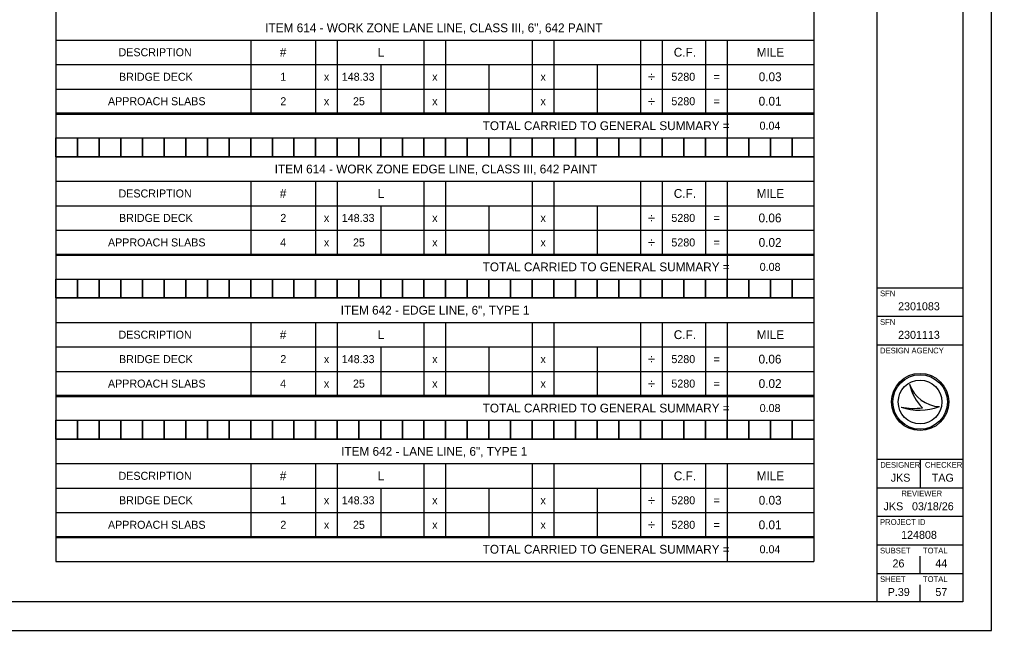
# Model space of a CAD drawing. Extents: x 0 to 34, y 0 to 22.
# Drawn here: x 17 to 34, y 0 to 10.69 of the extents above; entities that cross this region are included whole.
import ezdxf

# ---------------------------------------------------------------- set-up
doc = ezdxf.new("R2010")
doc.units = 0
for name, color, linetype in [('SH_Border', 7, 'Continuous'), ('SH_Cut_Line', 7, 'Continuous'), ('SH_Data', 7, 'Continuous'), ('SH_Text', 7, 'Continuous')]:
    doc.layers.add(name, color=color, linetype=linetype)

msp = doc.modelspace()

# ---------------------------------------------------------------- linework, layer by layer
at = {"layer": 'SH_Border'}
for p, q in [((32, 0.5), (32, 21.5)), ((32, 6), (33.5, 6)), ((32, 5.5), (33.5, 5.5)), ((32, 5), (33.5, 5)), ((32, 3), (33.5, 3)), ((32.75, 3), (32.75, 2.5)), ((32, 2.5), (33.5, 2.5)), ((32, 2), (33.5, 2)), ((32, 1.5), (33.5, 1.5)), ((32, 1), (33.5, 1))]:
    msp.add_line(p, q, dxfattribs=at)
msp.add_lwpolyline([(1.5, 21.5), (33.5, 21.5), (33.5, 0.5), (1.5, 0.5)], close=True, dxfattribs=at)
at = {"layer": 'SH_Cut_Line'}
msp.add_lwpolyline([(0, 0), (34, 0), (34, 22), (0, 22)], close=True, dxfattribs=at)
at = {"layer": 'SH_Data'}
for p, q in [((32.75, 5.675), (32.75, 5.675)), ((32.75, 5.175), (32.75, 5.175)), ((32.567, 4.31), (32.567, 4.31)), ((32.75, 4), (32.75, 4)), ((33.087, 3.919), (33.087, 3.919)), ((32.417, 3.91), (32.417, 3.91)), ((32.75, 1), (32.75, 1.3)), ((32.75, 0.5), (32.75, 0.8)), ((32.375, 0.675), (32.375, 0.675))]:
    msp.add_line(p, q, dxfattribs=at)
for radius in [0.5, 0.477, 0.477, 0.382]:
    msp.add_circle((32.75, 4), radius, dxfattribs=at)
for centre, radius, start, end in [((33.116, 4.498), 0.58, 198.9257, 198.9319), ((33.347, 4.47), 0.796, 191.6379, 191.6421), ((33.116, 4.498), 0.58, 198.9319, 267.1657), ((33.347, 4.47), 0.796, 191.6421, 226.0947), ((32.739, 4.87), 1.013, 251.4576, 290.0832), ((32.648, 5.154), 1.266, 259.4964, 259.4995), ((32.739, 4.87), 1.013, 251.4527, 251.4576), ((32.648, 5.154), 1.266, 259.4995, 276.6672)]:
    msp.add_arc(centre, radius, start, end, dxfattribs=at)
at = {"layer": 'SH_Text'}
for p, q in [((17.634, 11.531), (17.634, 9.038)), ((30.893, 11.531), (30.893, 9.038)), ((17.634, 10.334), (30.893, 10.334)), ((21.044, 10.334), (21.044, 9.06)), ((22.18, 10.334), (22.18, 9.06)), ((22.559, 10.334), (22.559, 9.06)), ((24.074, 10.334), (24.074, 9.06)), ((24.453, 10.334), (24.453, 9.06)), ((25.968, 10.334), (25.968, 9.06)), ((26.347, 10.334), (26.347, 9.06)), ((27.863, 10.334), (27.863, 9.06)), ((28.241, 10.334), (28.241, 9.06)), ((28.999, 10.334), (28.999, 9.06)), ((29.378, 10.334), (29.378, 9.06)), ((17.634, 9.905), (30.893, 9.905)), ((23.317, 9.905), (23.317, 9.06)), ((25.211, 9.905), (25.211, 9.06)), ((27.105, 9.905), (27.105, 9.06)), ((17.634, 9.477), (30.893, 9.477)), ((17.634, 9.06), (30.893, 9.06)), ((17.634, 9.06), (17.634, 6.567)), ((17.634, 9.038), (30.893, 9.038)), ((29.378, 9.038), (29.378, 8.621)), ((30.893, 9.06), (30.893, 6.567)), ((17.634, 8.621), (30.893, 8.621)), ((17.634, 8.291), (30.893, 8.291)), ((17.634, 7.863), (30.893, 7.863)), ((21.044, 7.863), (21.044, 6.589)), ((22.18, 7.863), (22.18, 6.589)), ((22.559, 7.863), (22.559, 6.589)), ((24.074, 7.863), (24.074, 6.589)), ((24.453, 7.863), (24.453, 6.589)), ((25.968, 7.863), (25.968, 6.589)), ((26.347, 7.863), (26.347, 6.589)), ((27.863, 7.863), (27.863, 6.589)), ((28.241, 7.863), (28.241, 6.589)), ((28.999, 7.863), (28.999, 6.589)), ((29.378, 7.863), (29.378, 6.589)), ((17.634, 7.435), (30.893, 7.435)), ((23.317, 7.435), (23.317, 6.589)), ((25.211, 7.435), (25.211, 6.589)), ((27.105, 7.435), (27.105, 6.589)), ((17.634, 7.007), (30.893, 7.007)), ((17.634, 6.589), (30.893, 6.589)), ((17.634, 6.589), (17.634, 4.097)), ((17.634, 6.567), (30.893, 6.567)), ((29.378, 6.567), (29.378, 6.15)), ((30.893, 6.589), (30.893, 4.097)), ((17.634, 6.15), (30.893, 6.15)), ((17.634, 5.821), (30.893, 5.821)), ((17.634, 5.392), (30.893, 5.392)), ((21.044, 5.392), (21.044, 4.119)), ((22.18, 5.392), (22.18, 4.119)), ((22.559, 5.392), (22.559, 4.119)), ((24.074, 5.392), (24.074, 4.119)), ((24.453, 5.392), (24.453, 4.119)), ((25.968, 5.392), (25.968, 4.119)), ((26.347, 5.392), (26.347, 4.119)), ((27.863, 5.392), (27.863, 4.119)), ((28.241, 5.392), (28.241, 4.119)), ((28.999, 5.392), (28.999, 4.119)), ((29.378, 5.392), (29.378, 4.119)), ((17.634, 4.964), (30.893, 4.964)), ((23.317, 4.964), (23.317, 4.119)), ((25.211, 4.964), (25.211, 4.119)), ((27.105, 4.964), (27.105, 4.119)), ((17.634, 4.536), (30.893, 4.536)), ((17.634, 4.119), (30.893, 4.119)), ((17.634, 4.119), (17.634, 1.626)), ((17.634, 4.097), (30.893, 4.097)), ((29.378, 4.097), (29.378, 3.68)), ((30.893, 4.119), (30.893, 1.626)), ((17.634, 3.68), (30.893, 3.68)), ((17.634, 3.35), (30.893, 3.35)), ((17.634, 2.922), (30.893, 2.922)), ((21.044, 2.922), (21.044, 1.648)), ((22.18, 2.922), (22.18, 1.648)), ((22.559, 2.922), (22.559, 1.648)), ((24.074, 2.922), (24.074, 1.648)), ((24.453, 2.922), (24.453, 1.648)), ((25.968, 2.922), (25.968, 1.648)), ((26.347, 2.922), (26.347, 1.648)), ((27.863, 2.922), (27.863, 1.648)), ((28.241, 2.922), (28.241, 1.648)), ((28.999, 2.922), (28.999, 1.648)), ((29.378, 2.922), (29.378, 1.648)), ((17.634, 2.494), (30.893, 2.494)), ((23.317, 2.494), (23.317, 1.648)), ((25.211, 2.494), (25.211, 1.648)), ((27.105, 2.494), (27.105, 1.648)), ((17.634, 2.065), (30.893, 2.065)), ((17.634, 1.648), (30.893, 1.648)), ((17.634, 1.648), (17.634, 1.209)), ((17.634, 1.626), (30.893, 1.626)), ((29.378, 1.626), (29.378, 1.209)), ((30.893, 1.648), (30.893, 1.209)), ((17.634, 1.209), (30.893, 1.209))]:
    msp.add_line(p, q, dxfattribs=at)
for points in [[(17.634, 8.621), (18.013, 8.621), (18.013, 8.291), (17.634, 8.291)], [(18.013, 8.621), (18.392, 8.621), (18.392, 8.291), (18.013, 8.291)], [(18.392, 8.621), (18.771, 8.621), (18.771, 8.291), (18.392, 8.291)], [(18.771, 8.621), (19.15, 8.621), (19.15, 8.291), (18.771, 8.291)], [(19.15, 8.621), (19.528, 8.621), (19.528, 8.291), (19.15, 8.291)], [(19.528, 8.621), (19.907, 8.621), (19.907, 8.291), (19.528, 8.291)], [(19.907, 8.621), (20.286, 8.621), (20.286, 8.291), (19.907, 8.291)], [(20.286, 8.621), (20.665, 8.621), (20.665, 8.291), (20.286, 8.291)], [(20.665, 8.621), (21.044, 8.621), (21.044, 8.291), (20.665, 8.291)], [(21.044, 8.621), (21.423, 8.621), (21.423, 8.291), (21.044, 8.291)], [(21.423, 8.621), (21.801, 8.621), (21.801, 8.291), (21.423, 8.291)], [(21.801, 8.621), (22.18, 8.621), (22.18, 8.291), (21.801, 8.291)], [(22.18, 8.621), (22.559, 8.621), (22.559, 8.291), (22.18, 8.291)], [(22.559, 8.621), (22.938, 8.621), (22.938, 8.291), (22.559, 8.291)], [(22.938, 8.621), (23.317, 8.621), (23.317, 8.291), (22.938, 8.291)], [(23.317, 8.621), (23.696, 8.621), (23.696, 8.291), (23.317, 8.291)], [(23.696, 8.621), (24.074, 8.621), (24.074, 8.291), (23.696, 8.291)], [(24.074, 8.621), (24.453, 8.621), (24.453, 8.291), (24.074, 8.291)], [(24.453, 8.621), (24.832, 8.621), (24.832, 8.291), (24.453, 8.291)], [(24.832, 8.621), (25.211, 8.621), (25.211, 8.291), (24.832, 8.291)], [(25.211, 8.621), (25.59, 8.621), (25.59, 8.291), (25.211, 8.291)], [(25.59, 8.621), (25.968, 8.621), (25.968, 8.291), (25.59, 8.291)], [(25.968, 8.621), (26.347, 8.621), (26.347, 8.291), (25.968, 8.291)], [(26.347, 8.621), (26.726, 8.621), (26.726, 8.291), (26.347, 8.291)], [(26.726, 8.621), (27.105, 8.621), (27.105, 8.291), (26.726, 8.291)], [(27.105, 8.621), (27.484, 8.621), (27.484, 8.291), (27.105, 8.291)], [(27.484, 8.621), (27.863, 8.621), (27.863, 8.291), (27.484, 8.291)], [(27.863, 8.621), (28.241, 8.621), (28.241, 8.291), (27.863, 8.291)], [(28.241, 8.621), (28.62, 8.621), (28.62, 8.291), (28.241, 8.291)], [(28.62, 8.621), (28.999, 8.621), (28.999, 8.291), (28.62, 8.291)], [(28.999, 8.621), (29.378, 8.621), (29.378, 8.291), (28.999, 8.291)], [(29.378, 8.621), (29.757, 8.621), (29.757, 8.291), (29.378, 8.291)], [(29.757, 8.621), (30.136, 8.621), (30.136, 8.291), (29.757, 8.291)], [(30.136, 8.621), (30.514, 8.621), (30.514, 8.291), (30.136, 8.291)], [(30.514, 8.621), (30.893, 8.621), (30.893, 8.291), (30.514, 8.291)], [(17.634, 6.15), (18.013, 6.15), (18.013, 5.821), (17.634, 5.821)], [(18.013, 6.15), (18.392, 6.15), (18.392, 5.821), (18.013, 5.821)], [(18.392, 6.15), (18.771, 6.15), (18.771, 5.821), (18.392, 5.821)], [(18.771, 6.15), (19.15, 6.15), (19.15, 5.821), (18.771, 5.821)], [(19.15, 6.15), (19.528, 6.15), (19.528, 5.821), (19.15, 5.821)], [(19.528, 6.15), (19.907, 6.15), (19.907, 5.821), (19.528, 5.821)], [(19.907, 6.15), (20.286, 6.15), (20.286, 5.821), (19.907, 5.821)], [(20.286, 6.15), (20.665, 6.15), (20.665, 5.821), (20.286, 5.821)], [(20.665, 6.15), (21.044, 6.15), (21.044, 5.821), (20.665, 5.821)], [(21.044, 6.15), (21.423, 6.15), (21.423, 5.821), (21.044, 5.821)], [(21.423, 6.15), (21.801, 6.15), (21.801, 5.821), (21.423, 5.821)], [(21.801, 6.15), (22.18, 6.15), (22.18, 5.821), (21.801, 5.821)], [(22.18, 6.15), (22.559, 6.15), (22.559, 5.821), (22.18, 5.821)], [(22.559, 6.15), (22.938, 6.15), (22.938, 5.821), (22.559, 5.821)], [(22.938, 6.15), (23.317, 6.15), (23.317, 5.821), (22.938, 5.821)], [(23.317, 6.15), (23.696, 6.15), (23.696, 5.821), (23.317, 5.821)], [(23.696, 6.15), (24.074, 6.15), (24.074, 5.821), (23.696, 5.821)], [(24.074, 6.15), (24.453, 6.15), (24.453, 5.821), (24.074, 5.821)], [(24.453, 6.15), (24.832, 6.15), (24.832, 5.821), (24.453, 5.821)], [(24.832, 6.15), (25.211, 6.15), (25.211, 5.821), (24.832, 5.821)], [(25.211, 6.15), (25.59, 6.15), (25.59, 5.821), (25.211, 5.821)], [(25.59, 6.15), (25.968, 6.15), (25.968, 5.821), (25.59, 5.821)], [(25.968, 6.15), (26.347, 6.15), (26.347, 5.821), (25.968, 5.821)], [(26.347, 6.15), (26.726, 6.15), (26.726, 5.821), (26.347, 5.821)], [(26.726, 6.15), (27.105, 6.15), (27.105, 5.821), (26.726, 5.821)], [(27.105, 6.15), (27.484, 6.15), (27.484, 5.821), (27.105, 5.821)], [(27.484, 6.15), (27.863, 6.15), (27.863, 5.821), (27.484, 5.821)], [(27.863, 6.15), (28.241, 6.15), (28.241, 5.821), (27.863, 5.821)], [(28.241, 6.15), (28.62, 6.15), (28.62, 5.821), (28.241, 5.821)], [(28.62, 6.15), (28.999, 6.15), (28.999, 5.821), (28.62, 5.821)], [(28.999, 6.15), (29.378, 6.15), (29.378, 5.821), (28.999, 5.821)], [(29.378, 6.15), (29.757, 6.15), (29.757, 5.821), (29.378, 5.821)], [(29.757, 6.15), (30.136, 6.15), (30.136, 5.821), (29.757, 5.821)], [(30.136, 6.15), (30.514, 6.15), (30.514, 5.821), (30.136, 5.821)], [(30.514, 6.15), (30.893, 6.15), (30.893, 5.821), (30.514, 5.821)], [(17.634, 3.68), (18.013, 3.68), (18.013, 3.35), (17.634, 3.35)], [(18.013, 3.68), (18.392, 3.68), (18.392, 3.35), (18.013, 3.35)], [(18.392, 3.68), (18.771, 3.68), (18.771, 3.35), (18.392, 3.35)], [(18.771, 3.68), (19.15, 3.68), (19.15, 3.35), (18.771, 3.35)], [(19.15, 3.68), (19.528, 3.68), (19.528, 3.35), (19.15, 3.35)], [(19.528, 3.68), (19.907, 3.68), (19.907, 3.35), (19.528, 3.35)], [(19.907, 3.68), (20.286, 3.68), (20.286, 3.35), (19.907, 3.35)], [(20.286, 3.68), (20.665, 3.68), (20.665, 3.35), (20.286, 3.35)], [(20.665, 3.68), (21.044, 3.68), (21.044, 3.35), (20.665, 3.35)], [(21.044, 3.68), (21.423, 3.68), (21.423, 3.35), (21.044, 3.35)], [(21.423, 3.68), (21.801, 3.68), (21.801, 3.35), (21.423, 3.35)], [(21.801, 3.68), (22.18, 3.68), (22.18, 3.35), (21.801, 3.35)], [(22.18, 3.68), (22.559, 3.68), (22.559, 3.35), (22.18, 3.35)], [(22.559, 3.68), (22.938, 3.68), (22.938, 3.35), (22.559, 3.35)], [(22.938, 3.68), (23.317, 3.68), (23.317, 3.35), (22.938, 3.35)], [(23.317, 3.68), (23.696, 3.68), (23.696, 3.35), (23.317, 3.35)], [(23.696, 3.68), (24.074, 3.68), (24.074, 3.35), (23.696, 3.35)], [(24.074, 3.68), (24.453, 3.68), (24.453, 3.35), (24.074, 3.35)], [(24.453, 3.68), (24.832, 3.68), (24.832, 3.35), (24.453, 3.35)], [(24.832, 3.68), (25.211, 3.68), (25.211, 3.35), (24.832, 3.35)], [(25.211, 3.68), (25.59, 3.68), (25.59, 3.35), (25.211, 3.35)], [(25.59, 3.68), (25.968, 3.68), (25.968, 3.35), (25.59, 3.35)], [(25.968, 3.68), (26.347, 3.68), (26.347, 3.35), (25.968, 3.35)], [(26.347, 3.68), (26.726, 3.68), (26.726, 3.35), (26.347, 3.35)], [(26.726, 3.68), (27.105, 3.68), (27.105, 3.35), (26.726, 3.35)], [(27.105, 3.68), (27.484, 3.68), (27.484, 3.35), (27.105, 3.35)], [(27.484, 3.68), (27.863, 3.68), (27.863, 3.35), (27.484, 3.35)], [(27.863, 3.68), (28.241, 3.68), (28.241, 3.35), (27.863, 3.35)], [(28.241, 3.68), (28.62, 3.68), (28.62, 3.35), (28.241, 3.35)], [(28.62, 3.68), (28.999, 3.68), (28.999, 3.35), (28.62, 3.35)], [(28.999, 3.68), (29.378, 3.68), (29.378, 3.35), (28.999, 3.35)], [(29.378, 3.68), (29.757, 3.68), (29.757, 3.35), (29.378, 3.35)], [(29.757, 3.68), (30.136, 3.68), (30.136, 3.35), (29.757, 3.35)], [(30.136, 3.68), (30.514, 3.68), (30.514, 3.35), (30.136, 3.35)], [(30.514, 3.68), (30.893, 3.68), (30.893, 3.35), (30.514, 3.35)]]:
    msp.add_lwpolyline(points, close=True, dxfattribs=at)

# ---------------------------------------------------------------- texts
at = {"layer": 'SH_Data'}
for s, height, p in [('SFN', 0.1, (32.05, 5.85)), ('2301083', 0.14, (32.366, 5.605)), ('SFN', 0.1, (32.05, 5.35)), ('2301113', 0.14, (32.366, 5.105)), ('DESIGN AGENCY', 0.1, (32.05, 4.85)), ('DESIGNER', 0.1, (32.054, 2.85)), ('CHECKER', 0.1, (32.835, 2.85)), ('JKS', 0.14, (32.237, 2.605)), ('TAG', 0.14, (32.955, 2.605)), ('REVIEWER', 0.1, (32.422, 2.35)), ('JKS', 0.14, (32.112, 2.105)), ('03/18/26', 0.14, (32.609, 2.105)), ('PROJECT ID', 0.1, (32.05, 1.85)), ('124808', 0.14, (32.419, 1.605)), ('SUBSET', 0.1, (32.05, 1.35)), ('TOTAL', 0.1, (32.8, 1.35)), ('26', 0.14, (32.268, 1.105)), ('44', 0.14, (33.016, 1.105)), ('SHEET', 0.1, (32.05, 0.85)), ('TOTAL', 0.1, (32.8, 0.85)), ('P.39', 0.14, (32.184, 0.605)), ('57', 0.14, (33.018, 0.605))]:
    msp.add_text(s, height=height, dxfattribs=at).set_placement(p)
at = {"layer": 'SH_Text'}
for s, height, p in [('ITEM 614 - WORK ZONE LANE LINE, CLASS III, 6", 642 PAINT', 0.154, (21.299, 10.471)), ('DESCRIPTION', 0.14, (18.733, 10.05)), ('#', 0.154, (21.553, 10.043)), ('L', 0.154, (23.266, 10.043)), ('C.F.', 0.154, (28.443, 10.043)), ('MILE', 0.154, (29.892, 10.043)), ('BRIDGE DECK', 0.14, (18.741, 9.621)), ('1', 0.14, (21.562, 9.621)), ('x', 0.14, (22.324, 9.621)), ('148.33', 0.14, (22.637, 9.621)), ('x', 0.14, (24.218, 9.621)), ('x', 0.14, (26.112, 9.621)), ('÷', 0.168, (27.99, 9.607)), ('5280', 0.14, (28.401, 9.621)), ('=', 0.14, (29.139, 9.621)), ('0.03', 0.154, (29.928, 9.614)), ('APPROACH SLABS', 0.14, (18.548, 9.193)), ('2', 0.14, (21.562, 9.193)), ('x', 0.14, (22.324, 9.193)), ('25', 0.14, (22.833, 9.193)), ('x', 0.14, (24.218, 9.193)), ('x', 0.14, (26.112, 9.193)), ('÷', 0.168, (27.99, 9.179)), ('5280', 0.14, (28.401, 9.193)), ('=', 0.14, (29.139, 9.193)), ('0.01', 0.154, (29.927, 9.186)), ('TOTAL CARRIED TO GENERAL SUMMARY =', 0.154, (25.101, 8.758)), ('0.04', 0.14, (29.943, 8.765)), ('ITEM 614 - WORK ZONE EDGE LINE, CLASS III, 642 PAINT', 0.154, (21.464, 8)), ('DESCRIPTION', 0.14, (18.733, 7.579)), ('#', 0.154, (21.553, 7.572)), ('L', 0.154, (23.266, 7.572)), ('C.F.', 0.154, (28.443, 7.572)), ('MILE', 0.154, (29.892, 7.572)), ('BRIDGE DECK', 0.14, (18.741, 7.151)), ('2', 0.14, (21.562, 7.151)), ('x', 0.14, (22.324, 7.151)), ('148.33', 0.14, (22.637, 7.151)), ('x', 0.14, (24.218, 7.151)), ('x', 0.14, (26.112, 7.151)), ('÷', 0.168, (27.99, 7.137)), ('5280', 0.14, (28.401, 7.151)), ('=', 0.14, (29.139, 7.151)), ('0.06', 0.154, (29.925, 7.144)), ('APPROACH SLABS', 0.14, (18.548, 6.722)), ('4', 0.14, (21.559, 6.722)), ('x', 0.14, (22.324, 6.722)), ('25', 0.14, (22.833, 6.722)), ('x', 0.14, (24.218, 6.722)), ('x', 0.14, (26.112, 6.722)), ('÷', 0.168, (27.99, 6.708)), ('5280', 0.14, (28.401, 6.722)), ('=', 0.14, (29.139, 6.722)), ('0.02', 0.154, (29.927, 6.715)), ('TOTAL CARRIED TO GENERAL SUMMARY =', 0.154, (25.101, 6.287)), ('0.08', 0.14, (29.945, 6.294)), ('ITEM 642 - EDGE LINE, 6", TYPE 1', 0.154, (22.618, 5.53)), ('DESCRIPTION', 0.14, (18.733, 5.108)), ('#', 0.154, (21.553, 5.101)), ('L', 0.154, (23.266, 5.101)), ('C.F.', 0.154, (28.443, 5.101)), ('MILE', 0.154, (29.892, 5.101)), ('BRIDGE DECK', 0.14, (18.741, 4.68)), ('2', 0.14, (21.562, 4.68)), ('x', 0.14, (22.324, 4.68)), ('148.33', 0.14, (22.637, 4.68)), ('x', 0.14, (24.218, 4.68)), ('x', 0.14, (26.112, 4.68)), ('÷', 0.168, (27.99, 4.666)), ('5280', 0.14, (28.401, 4.68)), ('=', 0.14, (29.139, 4.68)), ('0.06', 0.154, (29.925, 4.673)), ('APPROACH SLABS', 0.14, (18.548, 4.252)), ('4', 0.14, (21.559, 4.252)), ('x', 0.14, (22.324, 4.252)), ('25', 0.14, (22.833, 4.252)), ('x', 0.14, (24.218, 4.252)), ('x', 0.14, (26.112, 4.252)), ('÷', 0.168, (27.99, 4.238)), ('5280', 0.14, (28.401, 4.252)), ('=', 0.14, (29.139, 4.252)), ('0.02', 0.154, (29.927, 4.245)), ('TOTAL CARRIED TO GENERAL SUMMARY =', 0.154, (25.101, 3.817)), ('0.08', 0.14, (29.945, 3.824)), ('ITEM 642 - LANE LINE, 6", TYPE 1', 0.154, (22.626, 3.059)), ('DESCRIPTION', 0.14, (18.733, 2.638)), ('#', 0.154, (21.553, 2.631)), ('L', 0.154, (23.266, 2.631)), ('C.F.', 0.154, (28.443, 2.631)), ('MILE', 0.154, (29.892, 2.631)), ('BRIDGE DECK', 0.14, (18.741, 2.21)), ('1', 0.14, (21.562, 2.21)), ('x', 0.14, (22.324, 2.21)), ('148.33', 0.14, (22.637, 2.21)), ('x', 0.14, (24.218, 2.21)), ('x', 0.14, (26.112, 2.21)), ('÷', 0.168, (27.99, 2.196)), ('5280', 0.14, (28.401, 2.21)), ('=', 0.14, (29.139, 2.21)), ('0.03', 0.154, (29.928, 2.203)), ('APPROACH SLABS', 0.14, (18.548, 1.781)), ('2', 0.14, (21.562, 1.781)), ('x', 0.14, (22.324, 1.781)), ('25', 0.14, (22.833, 1.781)), ('x', 0.14, (24.218, 1.781)), ('x', 0.14, (26.112, 1.781)), ('÷', 0.168, (27.99, 1.767)), ('5280', 0.14, (28.401, 1.781)), ('=', 0.14, (29.139, 1.781)), ('0.01', 0.154, (29.927, 1.774)), ('TOTAL CARRIED TO GENERAL SUMMARY =', 0.154, (25.101, 1.346)), ('0.04', 0.14, (29.943, 1.353))]:
    msp.add_text(s, height=height, dxfattribs=at).set_placement(p)

doc.saveas('drawing.dxf')
